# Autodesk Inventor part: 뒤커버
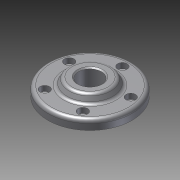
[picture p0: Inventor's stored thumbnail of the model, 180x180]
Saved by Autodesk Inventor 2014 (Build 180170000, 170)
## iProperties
Company: 한국ATC센터
Created: 2014-03
Part Number: 뒤커버
Document SubType Name: Modeling
Designer: KYOUNG IL JANG
Density: 1 g/cm^3
Material: 일반
Appearance: Default
Author: KYOUNG IL JANG
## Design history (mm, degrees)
sketch "스케치1"
  geometry: C1 r 20 at (0, 0); C2 r 35 at (0, 0); 1 further point
  constraints: 2 centre point, 2 coincident
  dimensions: "d0" = 40 diameter of C1; "d1" = 70 diameter of C2
extrude "돌출1" new body sketch "스케치1" distance "d2" = 5; taper "d3" = 0 deg
extrude "돌출2" join sketch "스케치1" distance "d4" = 8; taper "d5" = 0 deg
sketch "스케치2"
  geometry: C1 r 20 at (0, 0); 1 further point
  constraints: 1 centre point, 1 coincident
  dimensions: "d6" = 40 diameter of C1
extrude "돌출3" join sketch "스케치2" distance "d7" = 6; taper "d8" = -30 deg
sketch "스케치3"
  geometry: 2 further points
  constraints: 1 vertical alignment
  dimensions: "d9" = 27 distance of point (0, 0) point (0, 27)
hole "구멍1" sketch "스케치3" at (0, 27) diameter "d10" = 4.5; stored, may be unused: countersink angle "d14" = 90 deg, drill point angle "d16" = 118 deg; dims "d11" = 6, "d12" = 8, "d13" = 4.4, "d15" = 8
hole "구멍2" diameter "d22" = 19; stored, may be unused: countersink angle "d26" = 90 deg, drill point angle "d28" = 118 deg; dims "d20" = 10, "d21" = 10, "d23" = 6, "d24" = 30, "d25" = 3, "d27" = 8
fillet "모깎기1" dims "d29" = 3
chamfer "모따기1" distance "d30" = 1; stored, may be unused: second distance "d31" = 2, angle "d32" = 45 deg
node "솔리드1"
pattern_circular "원형 패턴1" dims angle "d18" = 360 deg
